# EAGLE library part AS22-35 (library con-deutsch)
DEUTSCH Connector
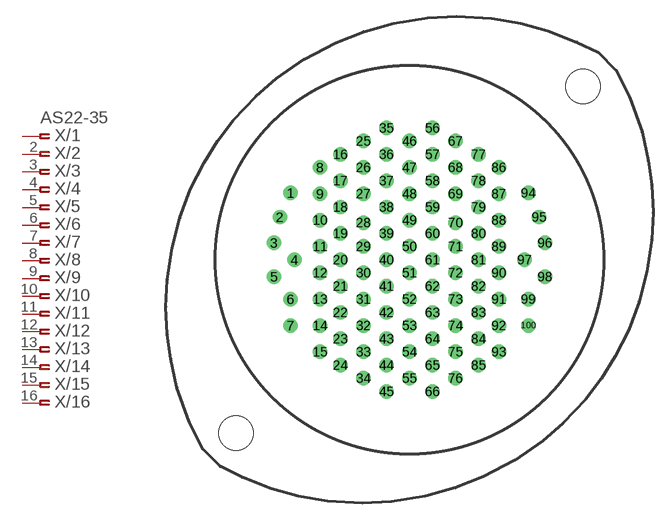
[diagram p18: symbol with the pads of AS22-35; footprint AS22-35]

Designator prefix X; gates /1=PINF_VAL /2=ASPINF /3=ASPINF /4=ASPINF /5=ASPINF /6=ASPINF /7=ASPINF /8=ASPINF /9=ASPINF /10=ASPINF /11=ASPINF /12=ASPINF /13=ASPINF /14=ASPINF /15=ASPINF /16=ASPINF /17=ASPINF /18=ASPINF /19=ASPINF /20=ASPINF /21=ASPINF /22=ASPINF /23=ASPINF /24=ASPINF /25=ASPINF /26=ASPINF /27=ASPINF /28=ASPINF /29=ASPINF /30=ASPINF /31=ASPINF /32=ASPINF /33=ASPINF /34=ASPINF /35=ASPINF /36=ASPINF /37=ASPINF /38=ASPINF /39=ASPINF /40=ASPINF /41=ASPINF /42=ASPINF /43=ASPINF /44=ASPINF /45=ASPINF /46=ASPINF /47=ASPINF /48=ASPINF /49=ASPINF /50=ASPINF /51=ASPINF /52=ASPINF /53=ASPINF /54=ASPINF /55=ASPINF /56=ASPINF /57=ASPINF /58=ASPINF /59=ASPINF /60=ASPINF /61=ASPINF /62=ASPINF /63=ASPINF /64=ASPINF /65=ASPINF /66=ASPINF /67=ASPINF /68=ASPINF /69=ASPINF /70=ASPINF /71=ASPINF /72=ASPINF /73=ASPINF /74=ASPINF /75=ASPINF /76=ASPINF /77=ASPINF /78=ASPINF /79=ASPINF /80=ASPINF /81=ASPINF /82=ASPINF /83=ASPINF /84=ASPINF /85=ASPINF /86=ASPINF /87=ASPINF /88=ASPINF /89=ASPINF /90=ASPINF /91=ASPINF /92=ASPINF /93=ASPINF /94=ASPINF /95=ASPINF /96=ASPINF /97=ASPINF /98=ASPINF /99=ASPINF /100=ASPINF

## AS22-35 (OC_FARNELL: unknown; OC_NEWARK: unknown)  [AS22-35]
1  /1:1  pas
2  /2:1  pas
3  /3:1  pas
4  /4:1  pas
5  /5:1  pas
6  /6:1  pas
7  /7:1  pas
8  /8:1  pas
9  /9:1  pas
10  /10:1  pas
11  /11:1  pas
12  /12:1  pas
13  /13:1  pas
14  /14:1  pas
15  /15:1  pas
16  /16:1  pas
17  /17:1  pas
18  /18:1  pas
19  /19:1  pas
20  /20:1  pas
21  /21:1  pas
22  /22:1  pas
23  /23:1  pas
24  /24:1  pas
25  /25:1  pas
26  /26:1  pas
27  /27:1  pas
28  /28:1  pas
29  /29:1  pas
30  /30:1  pas
31  /31:1  pas
32  /32:1  pas
33  /33:1  pas
34  /34:1  pas
35  /35:1  pas
36  /36:1  pas
37  /37:1  pas
38  /38:1  pas
39  /39:1  pas
40  /40:1  pas
41  /41:1  pas
42  /42:1  pas
43  /43:1  pas
44  /44:1  pas
45  /45:1  pas
46  /46:1  pas
47  /47:1  pas
48  /48:1  pas
49  /49:1  pas
50  /50:1  pas
51  /51:1  pas
52  /52:1  pas
53  /53:1  pas
54  /54:1  pas
55  /55:1  pas
56  /56:1  pas
57  /57:1  pas
58  /58:1  pas
59  /59:1  pas
60  /60:1  pas
61  /61:1  pas
62  /62:1  pas
63  /63:1  pas
64  /64:1  pas
65  /65:1  pas
66  /66:1  pas
67  /67:1  pas
68  /68:1  pas
69  /69:1  pas
70  /70:1  pas
71  /71:1  pas
72  /72:1  pas
73  /73:1  pas
74  /74:1  pas
75  /75:1  pas
76  /76:1  pas
77  /77:1  pas
78  /78:1  pas
79  /79:1  pas
80  /80:1  pas
81  /81:1  pas
82  /82:1  pas
83  /83:1  pas
84  /84:1  pas
85  /85:1  pas
86  /86:1  pas
87  /87:1  pas
88  /88:1  pas
89  /89:1  pas
90  /90:1  pas
91  /91:1  pas
92  /92:1  pas
93  /93:1  pas
94  /94:1  pas
95  /95:1  pas
96  /96:1  pas
97  /97:1  pas
98  /98:1  pas
99  /99:1  pas
100  /100:1  pas

## Footprint AS22-35 (pad centres in mm)
DEUTSCH Connector
drill 0.813 round: 1 -10.871,6.121; 2 -11.862,3.912; 3 -12.395,1.549; 4 -10.541,0; 5 -12.395,-1.549; 6 -10.871,-3.607; 7 -10.871,-6.02; 8 -8.179,8.458; 9 -8.179,6.045; 10 -8.179,3.632; 11 -8.179,1.219; 12 -8.179,-1.194; 13 -8.179,-3.607; 14 -8.179,-6.02; 15 -8.179,-8.433; 16 -6.325,9.652; 17 -6.325,7.239; 18 -6.325,4.826; 19 -6.325,2.413; 20 -6.325,0; 21 -6.325,-2.413; 22 -6.325,-4.826; 23 -6.325,-7.239; 24 -6.325,-9.652; 25 -4.216,10.871; 26 -4.216,8.458; 27 -4.216,6.045; 28 -4.216,3.404; 29 -4.216,1.219; 30 -4.216,-1.194; 31 -4.216,-3.607; 32 -4.216,-6.02; 33 -4.216,-8.433; 34 -4.216,-10.846; 35 -2.108,12.065; 36 -2.108,9.652; 37 -2.108,7.239; 38 -2.108,4.826; 39 -2.108,2.413; 40 -2.108,0; 41 -2.108,-2.413; 42 -2.108,-4.826; 43 -2.108,-7.239; 44 -2.108,-9.652; 45 -2.108,-12.065; 46 0,10.871; 47 0,8.458; 48 0,6.045; 49 0,3.632; 50 0,1.219; 51 0,-1.194; 52 0,-3.607; 53 0,-6.02; 54 0,-8.433; 55 0,-10.846; 56 2.108,12.065; 57 2.108,9.652; 58 2.108,7.239; 59 2.108,4.826; 60 2.108,2.413; 61 2.108,0; 62 2.108,-2.413; 63 2.108,-4.826; 64 2.108,-7.239; 65 2.108,-9.652; 66 2.108,-12.065; 67 4.216,10.871; 68 4.216,8.458; 69 4.216,6.045; 70 4.216,3.404; 71 4.216,1.219; 72 4.216,-1.194; 73 4.216,-3.607; 74 4.216,-6.02; 75 4.216,-8.433; 76 4.216,-10.846; 77 6.325,9.652; 78 6.325,7.239; 79 6.325,4.826; 80 6.325,2.413; 81 6.325,0; 82 6.325,-2.413; 83 6.325,-4.826; 84 6.325,-7.239; 85 6.325,-9.652; 86 8.179,8.458; 87 8.179,6.045; 88 8.179,3.632; 89 8.179,1.219; 90 8.179,-1.194; 91 8.179,-3.607; 92 8.179,-6.02; 93 8.179,-8.433; 94 10.871,6.121; 95 11.862,3.912; 96 12.395,1.549; 97 10.541,0; 98 12.395,-1.549; 99 10.871,-3.607; 100 10.871,-6.02
hole 3.2 at -15.875,-15.875
hole 3.2 at 15.875,15.875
